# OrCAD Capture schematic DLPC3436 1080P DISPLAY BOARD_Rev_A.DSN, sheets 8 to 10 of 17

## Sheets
8 P12: DLPA3000 PMIC: size D
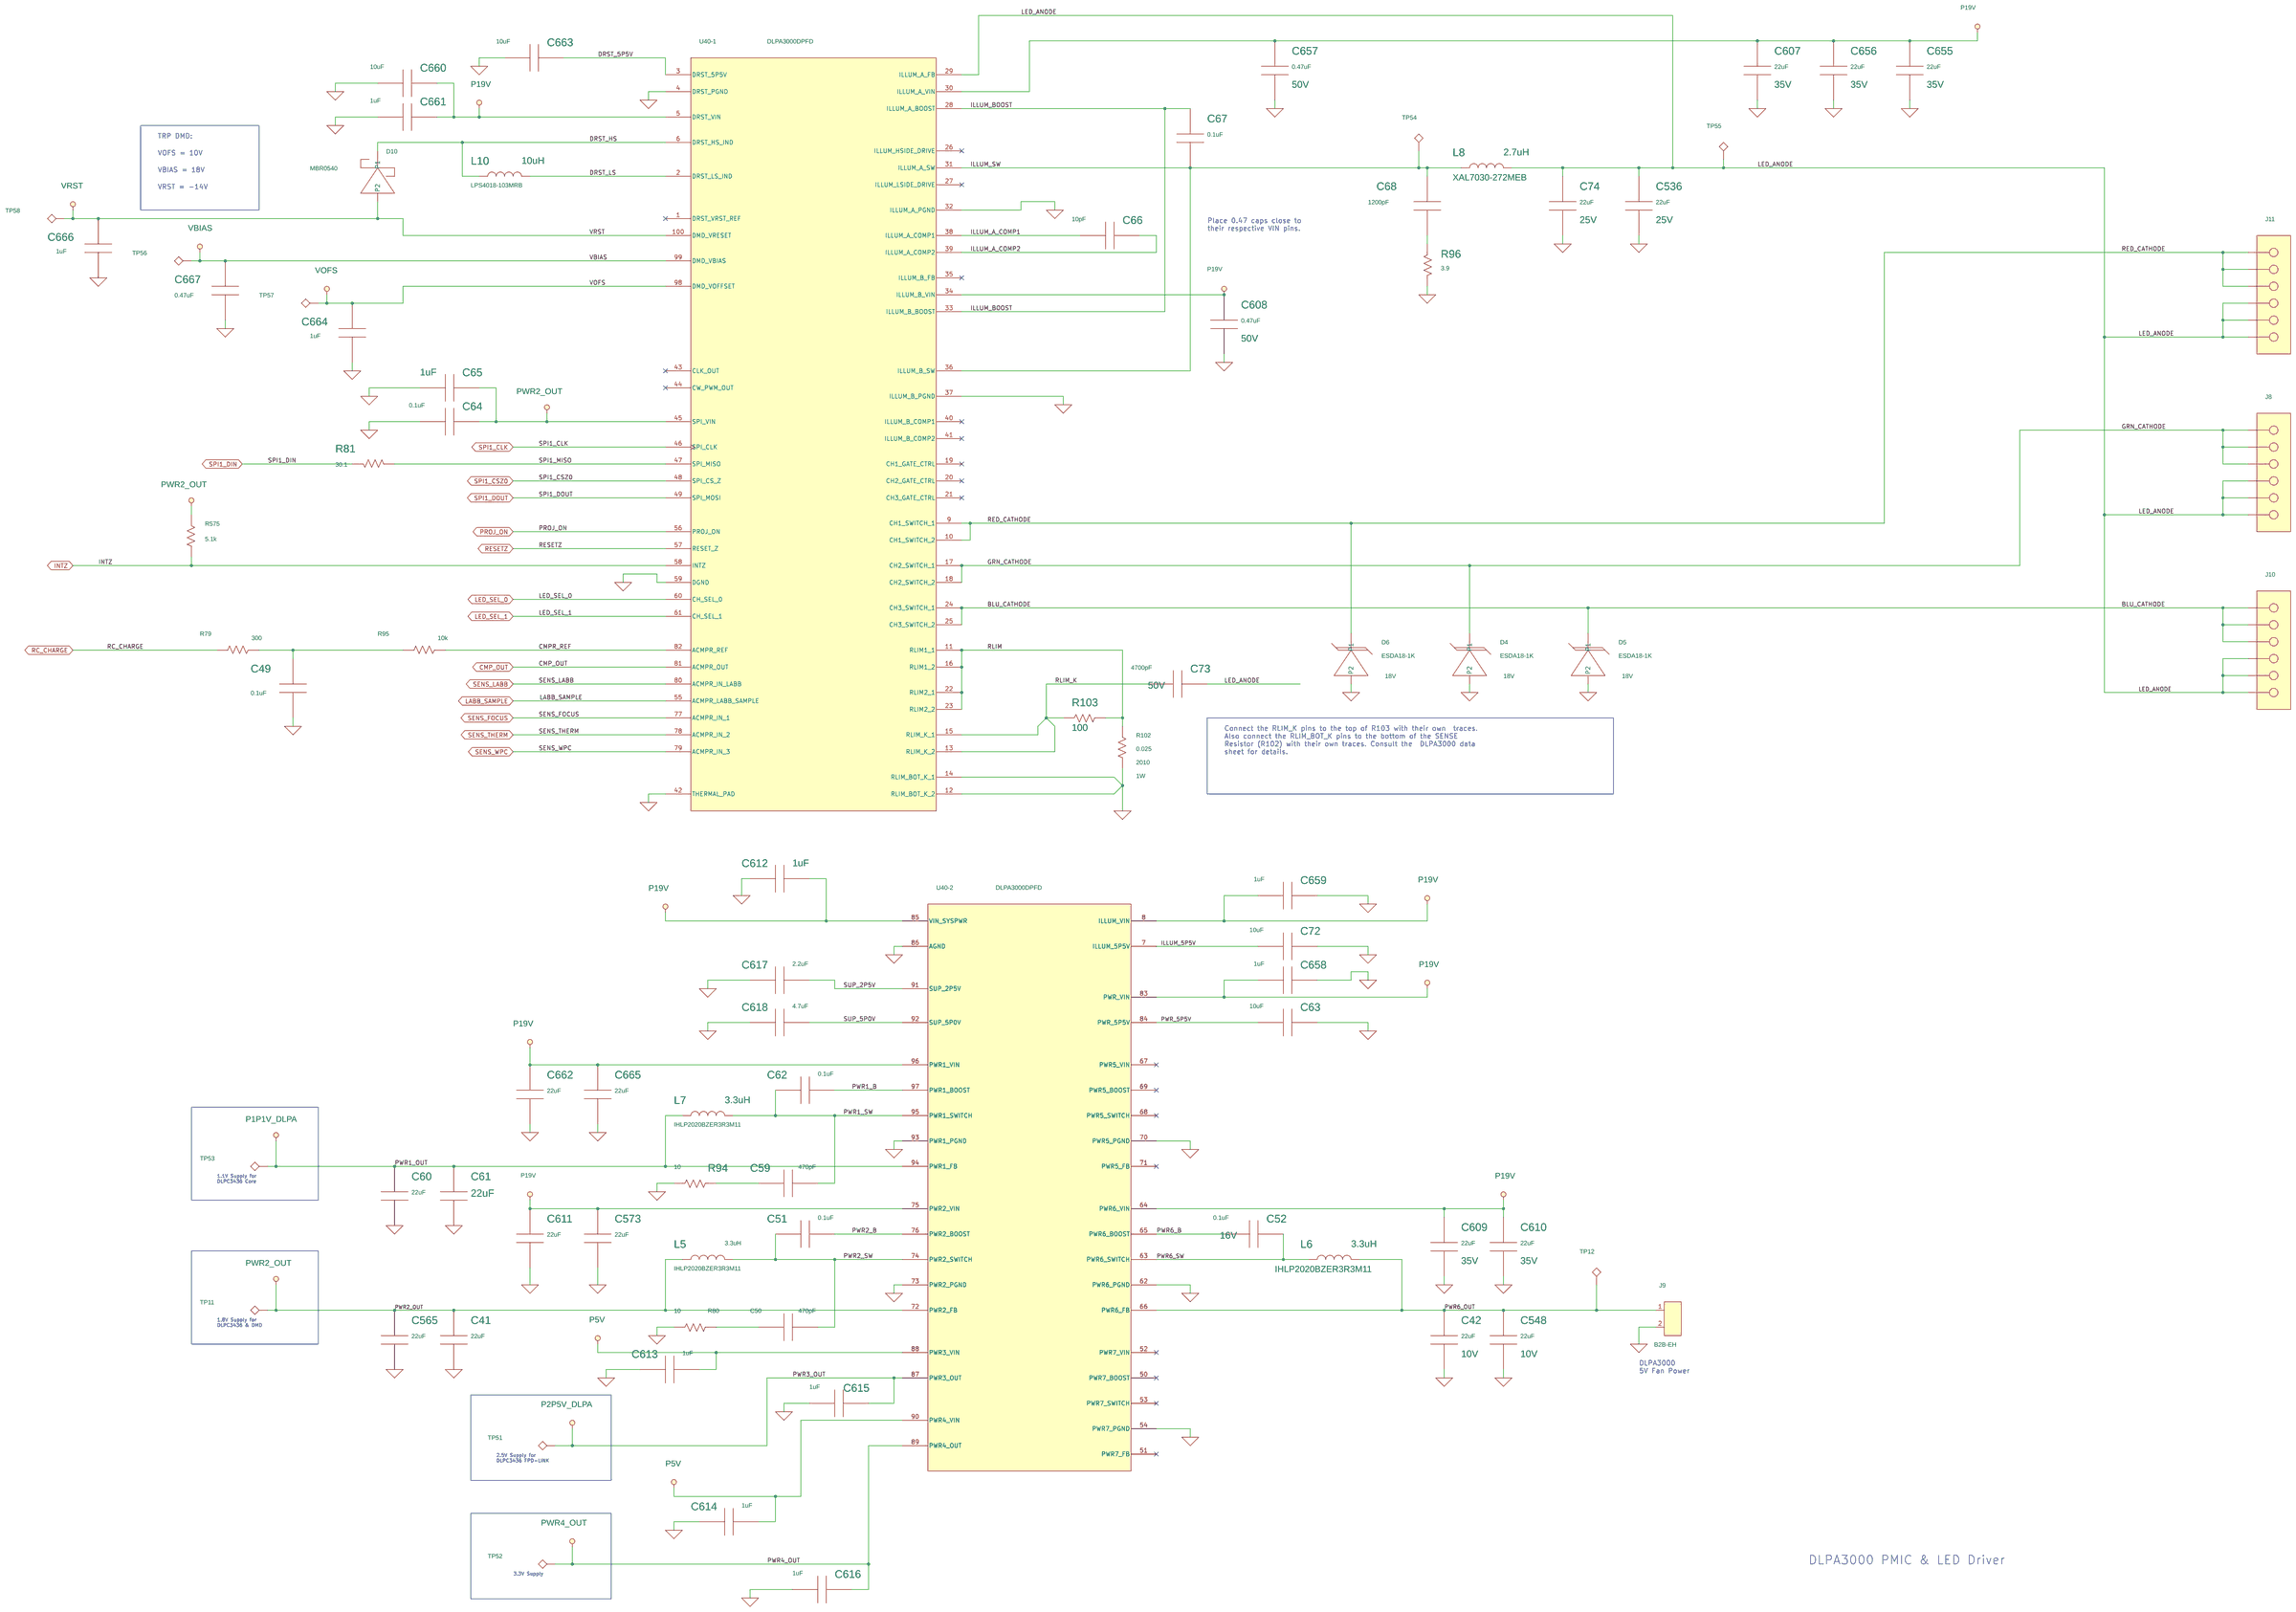
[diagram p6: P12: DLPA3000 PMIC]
9 P03: Parallel Video Input: size D
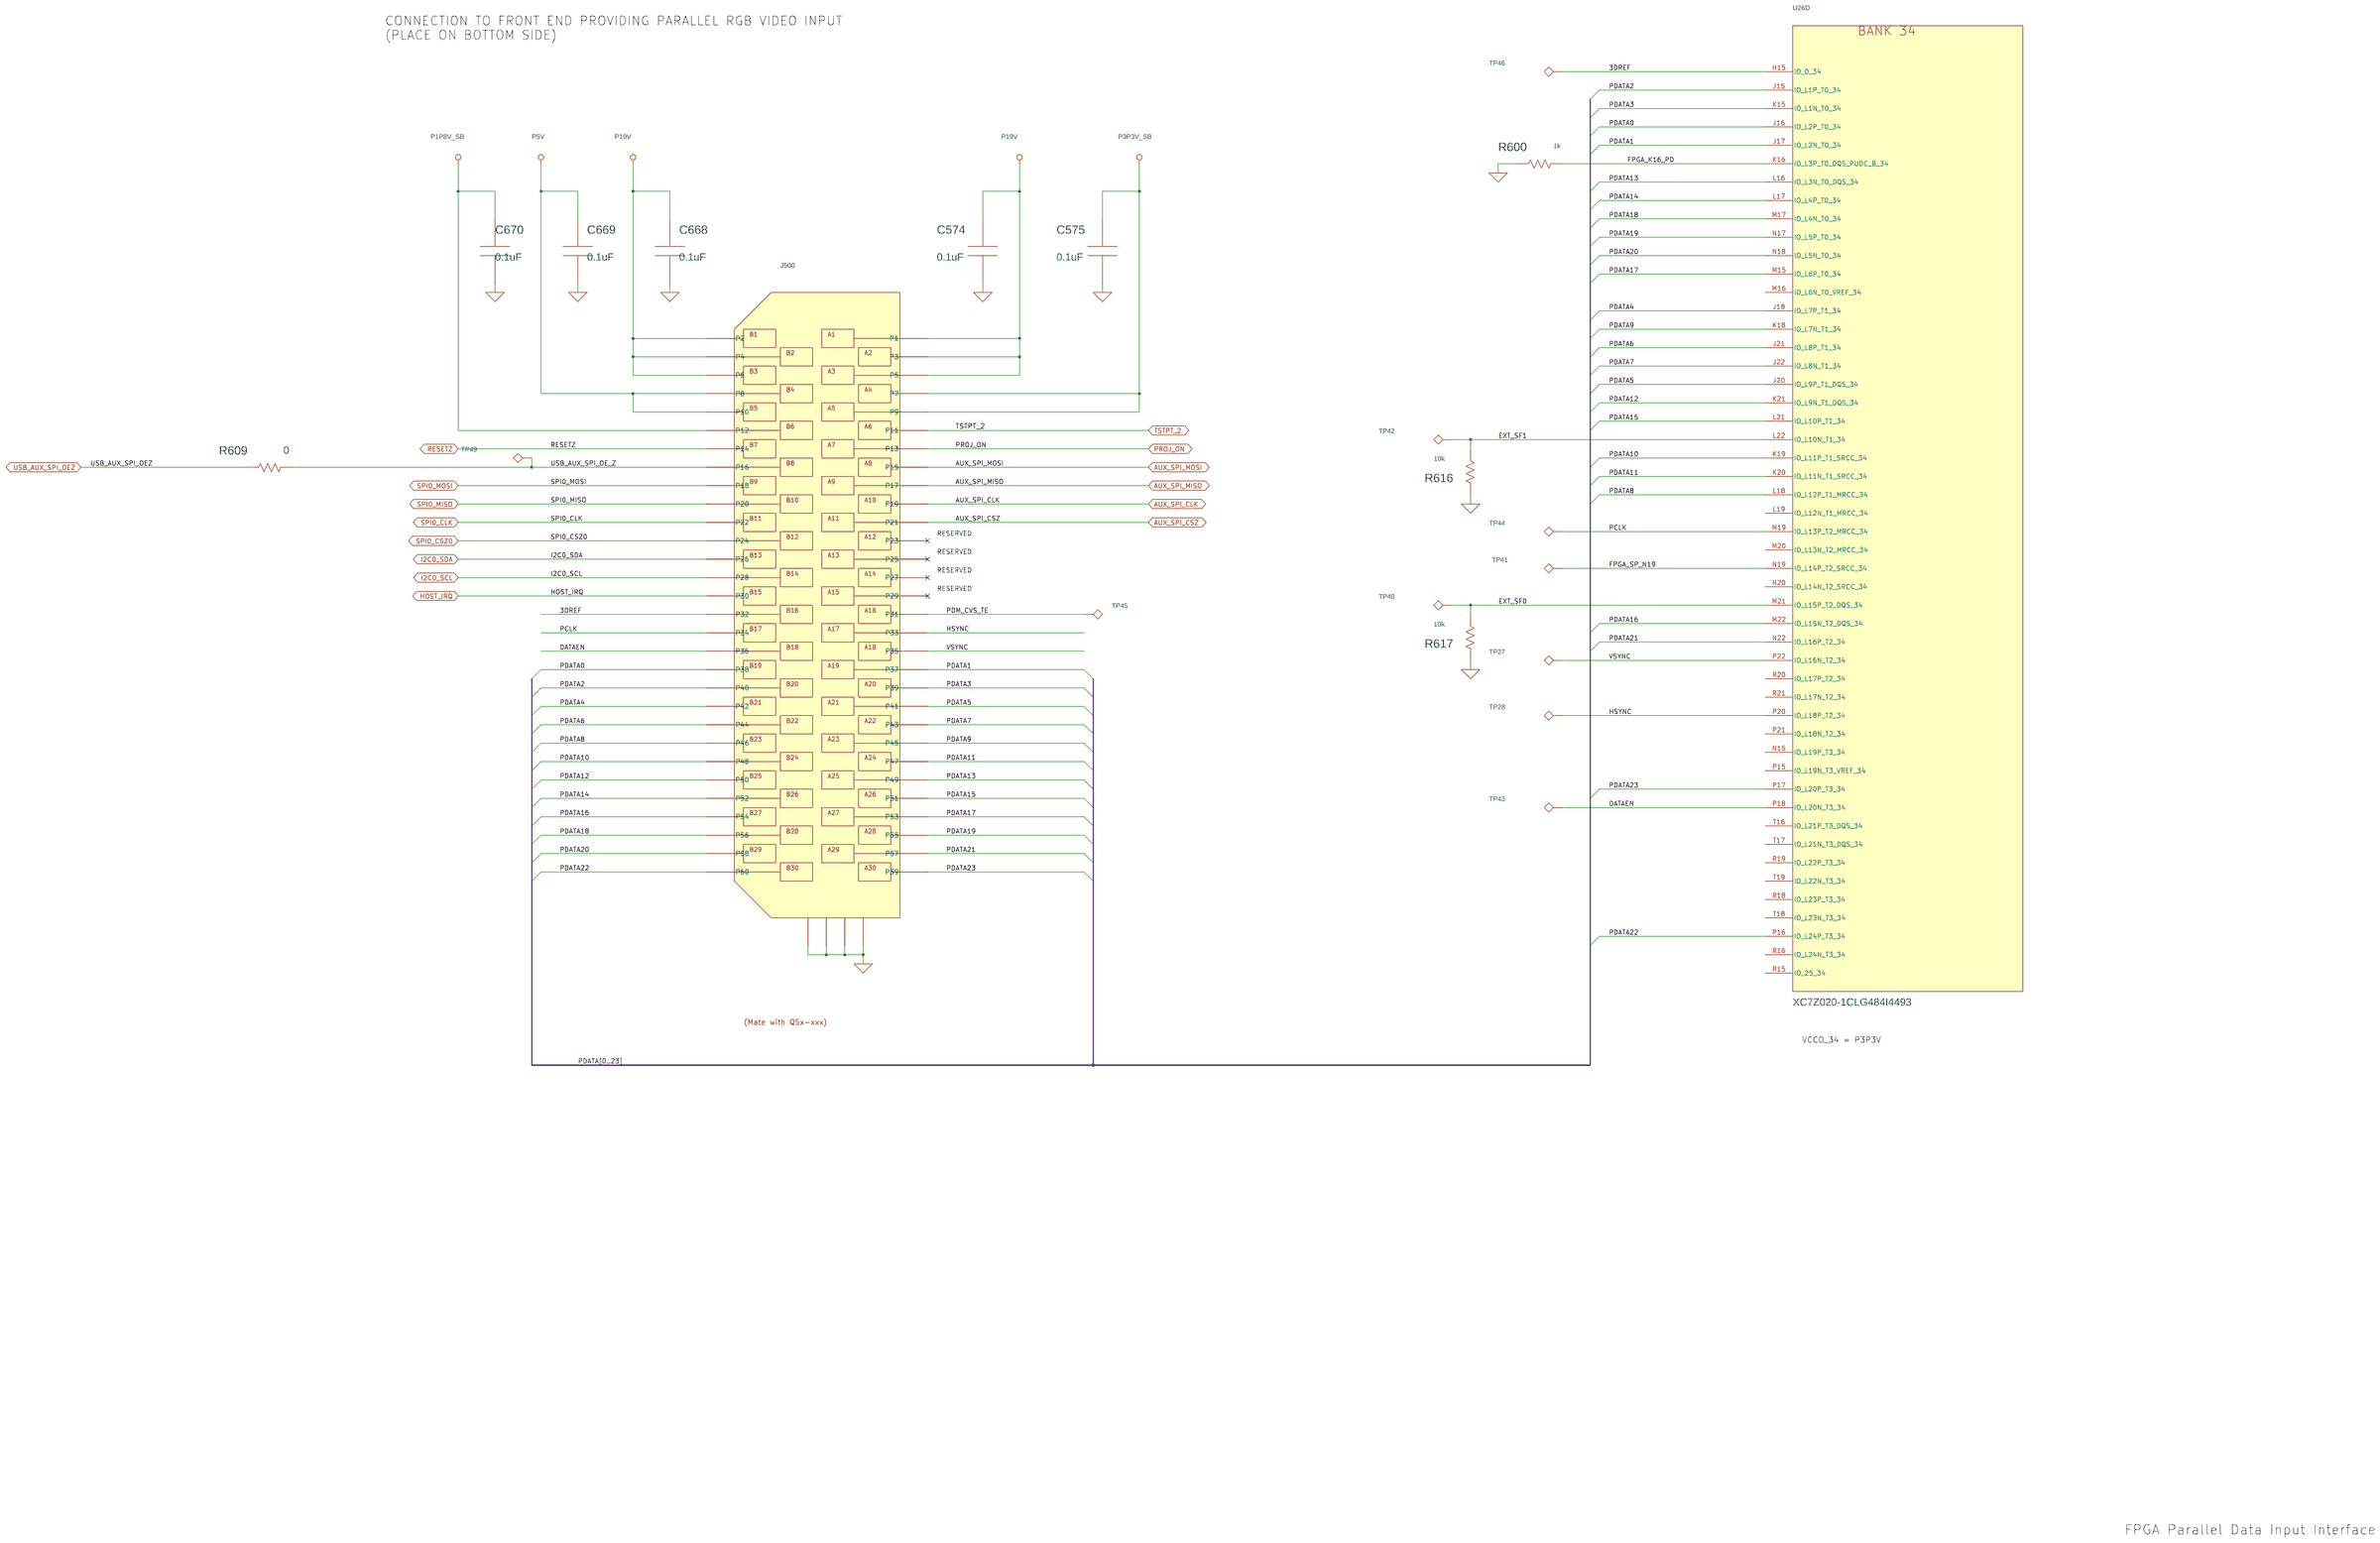
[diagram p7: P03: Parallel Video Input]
10 P14: Actuator Driver: size D
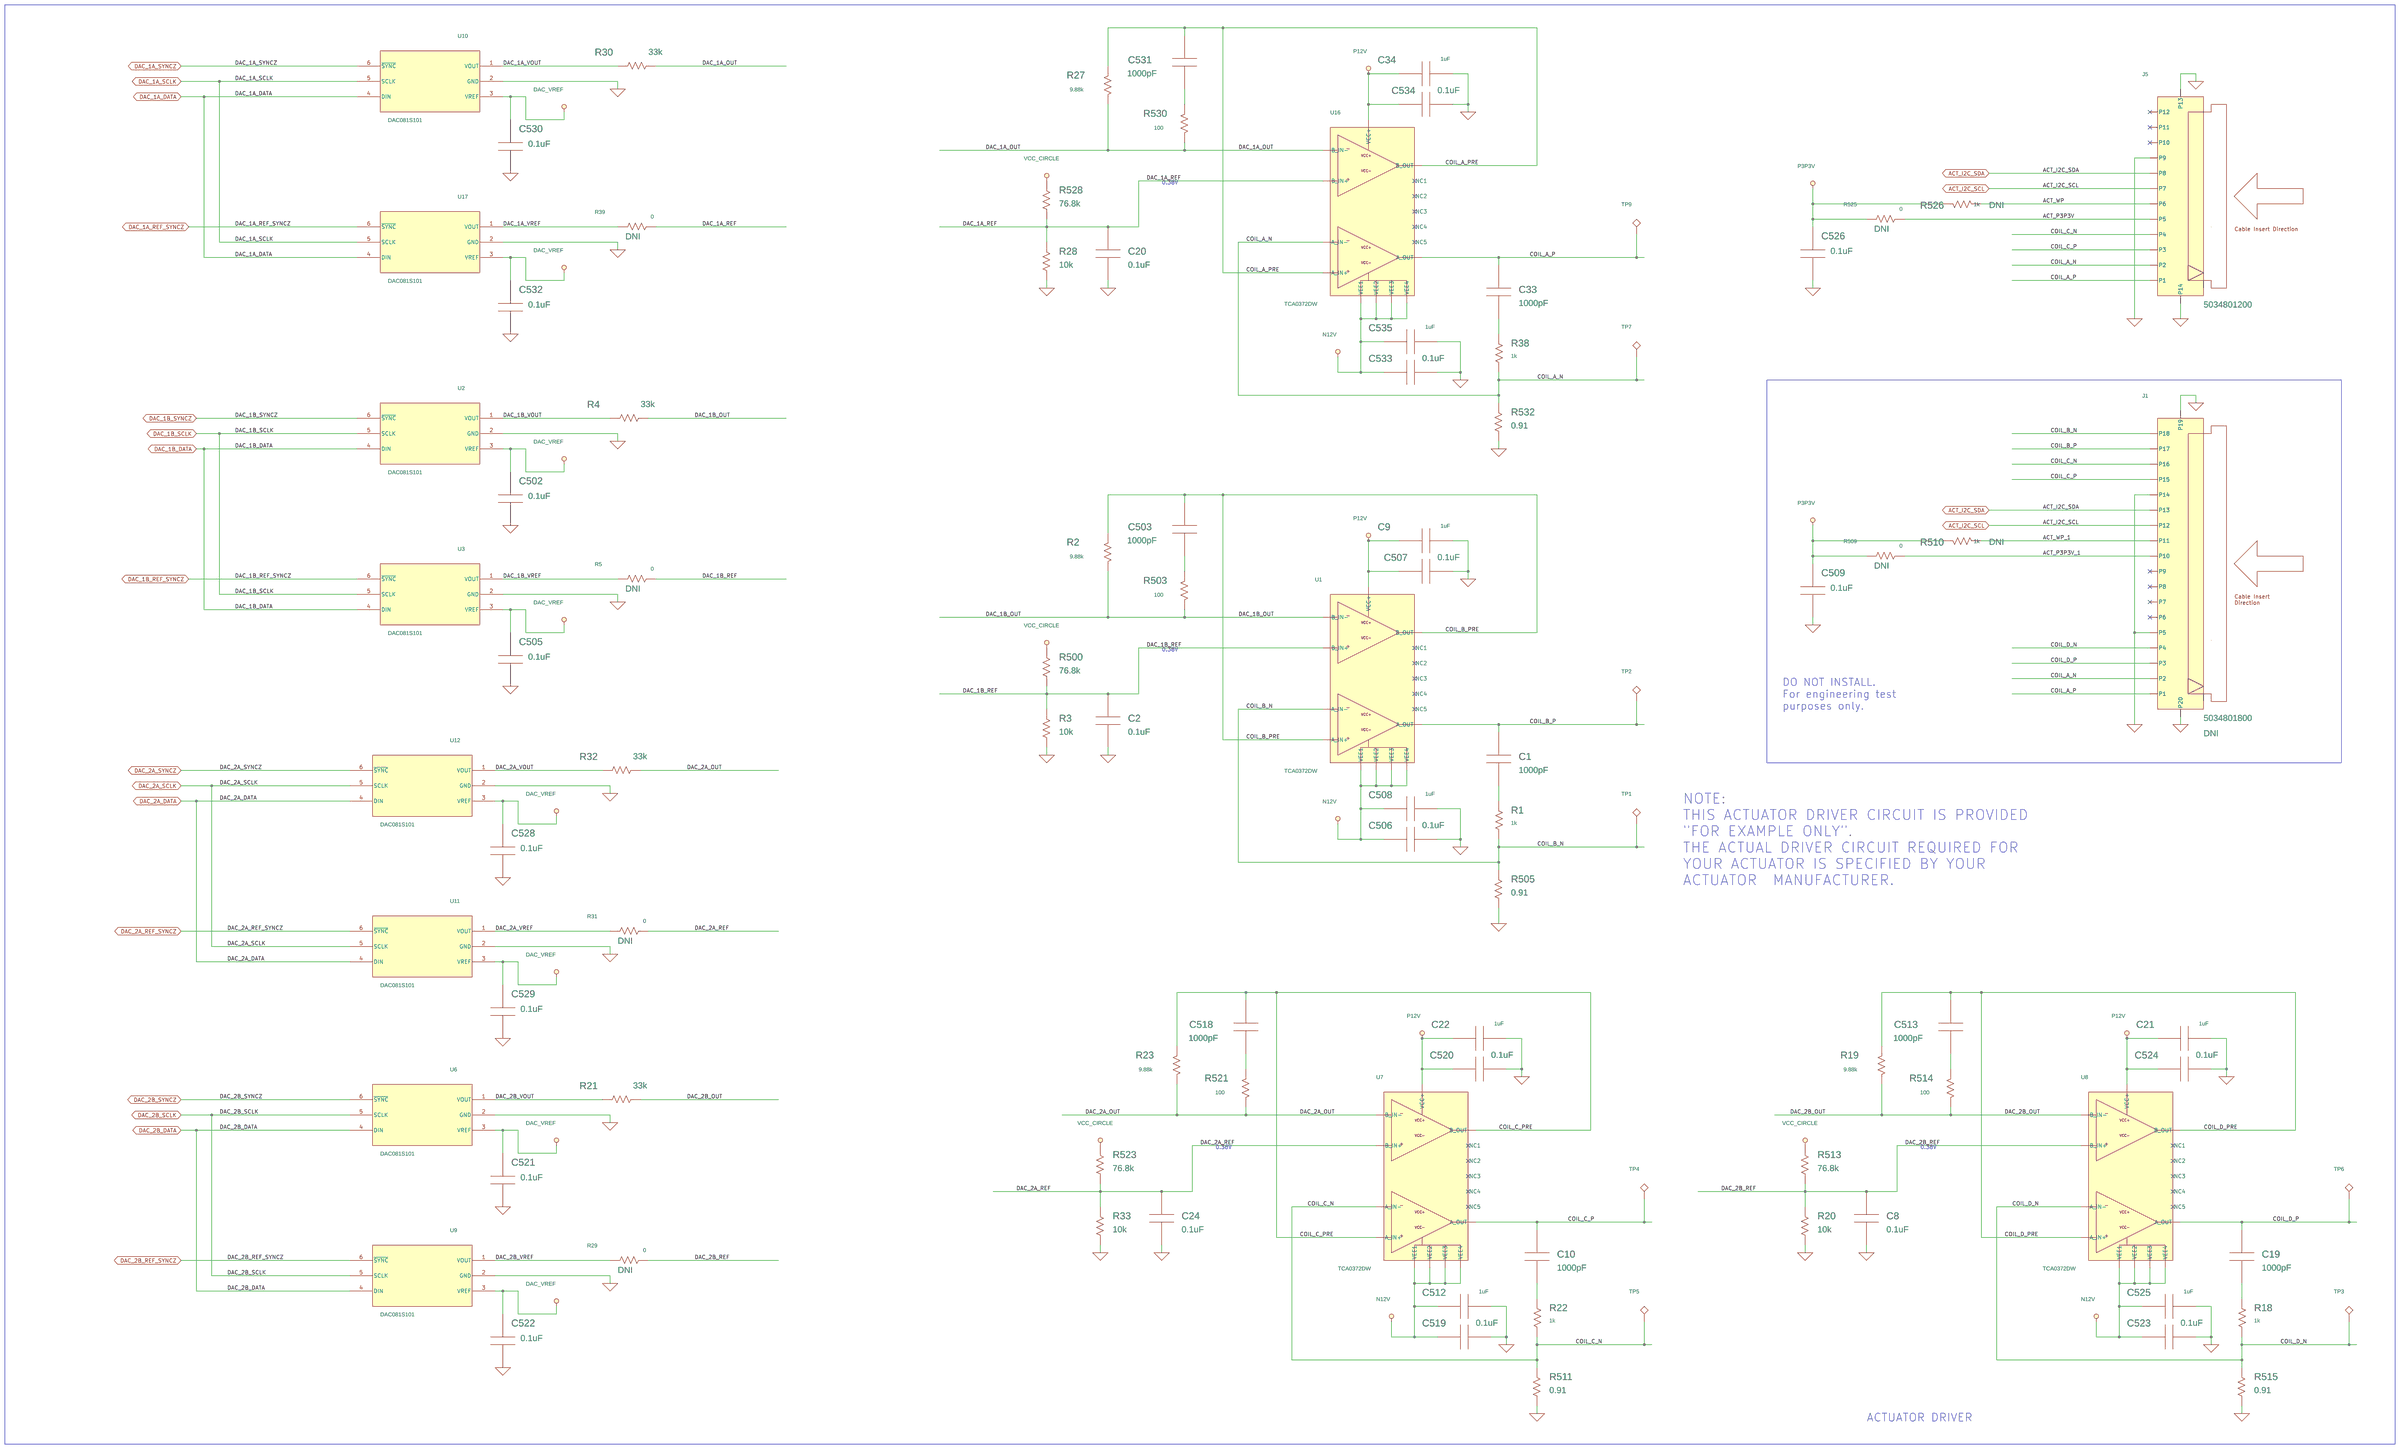
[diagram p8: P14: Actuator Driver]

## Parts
sheet P03: Parallel Video Input
C574  0.1uF  [0402_AVXA]
C575  0.1uF  [0402_AVXA]
C668  0.1uF  [0402_AVXA]
C669  0.1uF  [0402_AVXA]
C670  0.1uF  [0402_AVXA]
J500  QTH-030-03-L-D-A  [Samtec_QTH-030-xx-x-D-A]
R600  1k  [0402]
R609  0  [0402]
R616  10k  [0402]
R617  10k  [0402]
TP27  TP_WHT  [KEYSTONE_TP_MINIATURE]
TP28  TP40  [TP40]
TP40  TP40  [TP40]
TP41  TP,12mil Drill,32mil Pad  [HOLE_PLATED_12mil_DRILL_32mil_PAD]
TP42  TP40  [TP40]
TP43  TP40  [TP40]
TP44  TP40  [TP40]
TP45  TP,12mil Drill,32mil Pad  [HOLE_PLATED_12mil_DRILL_32mil_PAD]
TP46  TP40  [TP40]
TP49  TP,12mil Drill,32mil Pad  [HOLE_PLATED_12mil_DRILL_32mil_PAD]
U26  XC7Z020-1CLG484I4493  [Xilinx_CLG484]  (sections A,B,C,D,E,F,G,H,I,J)
sheet P12: DLPA3000 PMIC
C41  22uF  [0603]
C42  22uF  [0603]
C49  0.1uF  [0402_AVXA]
C50  470pF  [0603]
C51  0.1uF  [0402_AVXA]
C52  0.1uF  [0402_AVXA]
C59  470pF  [0603]
C60  22uF  [0603]
C61  22uF  [0603]
C62  0.1uF  [0402_AVXA]
C63  10uF  [0603]
C64  0.1uF  [0402_AVXA]
C65  1uF  [0402]
C66  10pF  [0402_AVXA]
C67  0.1uF  [0402_AVXA]
C68  1200pF  [1206]
C72  10uF  [0603]
C73  4700pF  [0402]
C74  22uF  [1210]
C536  22uF  [1210]
C548  22uF  [0603]
C565  22uF  [0603]
C573  22uF  [0805]
C607  22uF  [1210]
C608  0.47uF  [0402]
C609  22uF  [0805]
C610  22uF  [0805]
C611  22uF  [0805]
C612  1uF  [0402]
C613  1uF  [0402]
C614  1uF  [0402]
C615  1uF  [0402]
C616  1uF  [0402]
C617  2.2uF  [0402]
C618  4.7uF  [0402]
C655  22uF  [1210]
C656  22uF  [1210]
C657  0.47uF  [0402]
C658  1uF  [0402]
C659  1uF  [0402]
C660  10uF  [0805]
C661  1uF  [0402]
C662  22uF  [0805]
C663  10uF  [0603]
C664  1uF  [0603]
C665  22uF  [0805]
C666  1uF  [0603]
C667  0.47uF  [0603]
D4  ESDA18-K  [SOD523]
D5  ESDA18-K  [SOD523]
D6  ESDA18-K  [SOD523]
D10  MBR0540  [SOD123]
J8  087438-0643  [Molex_0874380643]
J9  B2B-EH  [JST_B2B_EH_A]
J10  087438-0643  [Molex_0874380643]
J11  087438-0643  [Molex_0874380643]
L5  3.3uH  [IHLP2020BZER]
L6  3.3uH  [IHLP2020BZER]
L7  3.3uH  [IHLP2020BZER]
L8  2.7uH  [Coilcraft_XAL70300]
L10  10uH  [Coilcraft_LPS4018_MR]
R79  300  [0402]
R80  10  [0603]
R81  30.1  [0402]
R94  10  [0603]
R95  10k  [0402]
R96  3.9  [1210]
R102  0.025  [2010]
R103  100  [0402]
R575  5.1k  [0402]
TP11  TP,40mil Drill,60mil Pad  [HOLE_PLATED_40mil_DRILL_60mil_PAD]
TP12  TP,40mil Drill,60mil Pad  [HOLE_PLATED_40mil_DRILL_60mil_PAD]
TP51  TP,40mil Drill,60mil Pad  [HOLE_PLATED_40mil_DRILL_60mil_PAD]
TP52  TP,40mil Drill,60mil Pad  [HOLE_PLATED_40mil_DRILL_60mil_PAD]
TP53  TP,40mil Drill,60mil Pad  [HOLE_PLATED_40mil_DRILL_60mil_PAD]
TP54  TP,40mil Drill,60mil Pad  [HOLE_PLATED_40mil_DRILL_60mil_PAD]
TP55  TP,40mil Drill,60mil Pad  [HOLE_PLATED_40mil_DRILL_60mil_PAD]
TP56  TP,40mil Drill,60mil Pad  [HOLE_PLATED_40mil_DRILL_60mil_PAD]
TP57  TP,40mil Drill,60mil Pad  [HOLE_PLATED_40mil_DRILL_60mil_PAD]
TP58  TP,40mil Drill,60mil Pad  [HOLE_PLATED_40mil_DRILL_60mil_PAD]
U40  DLPA3000  [PAD3000_PQFP_100]  (sections -1,-2)
sheet P14: Actuator Driver
C1  1000pF  [0603]
C2  0.1uF  [0805]
C8  0.1uF  [0805]
C9  1uF  [0402]
C10  1000pF  [0603]
C19  1000pF  [0603]
C20  0.1uF  [0805]
C21  1uF  [0402]
C22  1uF  [0402]
C24  0.1uF  [0805]
C33  1000pF  [0603]
C34  1uF  [0402]
C502  0.1uF  [0402]
C503  1000pF  [0603]
C505  0.1uF  [0402]
C506  0.1uF  [0402]
C507  0.1uF  [0402]
C508  1uF  [0402]
C509  0.1uF  [0402]
C512  1uF  [0402]
C513  1000pF  [0603]
C518  1000pF  [0603]
C519  0.1uF  [0402]
C520  0.1uF  [0402]
C521  0.1uF  [0402]
C522  0.1uF  [0402]
C523  0.1uF  [0402]
C524  0.1uF  [0402]
C525  1uF  [0402]
C526  0.1uF  [0402]
C528  0.1uF  [0402]
C529  0.1uF  [0402]
C530  0.1uF  [0402]
C531  1000pF  [0603]
C532  0.1uF  [0402]
C533  0.1uF  [0402]
C534  0.1uF  [0402]
C535  1uF  [0402]
J1  5034801800  [Molex_5034801800_2GPADS]
J5  5034801200  [Molex_5034801200_2GPADS]
R1  1k  [0603]
R2  9.88k  [0805]
R3  10k  [0603]
R4  33k  [0402]
R5  0  [0402]
R18  1k  [0603]
R19  9.88k  [0805]
R20  10k  [0603]
R21  33k  [0402]
R22  1k  [0603]
R23  9.88k  [0805]
R27  9.88k  [0805]
R28  10k  [0603]
R29  0  [0402]
R30  33k  [0402]
R31  0  [0402]
R32  33k  [0402]
R33  10k  [0603]
R38  1k  [0603]
R39  0  [0402]
R500  76.8k  [0603]
R503  100  [0603]
R505  0.91  [0805]
R509  0  [0402]
R510  1k  [0402]
R511  0.91  [0805]
R513  76.8k  [0603]
R514  100  [0603]
R515  0.91  [0805]
R521  100  [0603]
R523  76.8k  [0603]
R525  0  [0402]
R526  1k  [0402]
R528  76.8k  [0603]
R530  100  [0603]
R532  0.91  [0805]
TP1  TP,40mil Drill,60mil Pad  [HOLE_PLATED_40mil_DRILL_60mil_PAD]
TP2  TP,40mil Drill,60mil Pad  [HOLE_PLATED_40mil_DRILL_60mil_PAD]
TP3  TP,40mil Drill,60mil Pad  [HOLE_PLATED_40mil_DRILL_60mil_PAD]
TP4  TP,40mil Drill,60mil Pad  [HOLE_PLATED_40mil_DRILL_60mil_PAD]
TP5  TP,40mil Drill,60mil Pad  [HOLE_PLATED_40mil_DRILL_60mil_PAD]
TP6  TP,40mil Drill,60mil Pad  [HOLE_PLATED_40mil_DRILL_60mil_PAD]
TP7  TP,40mil Drill,60mil Pad  [HOLE_PLATED_40mil_DRILL_60mil_PAD]
TP9  TP,40mil Drill,60mil Pad  [HOLE_PLATED_40mil_DRILL_60mil_PAD]
U1  TCA0372DW  [ONSEMI_SOIC16W_DW_CASE751G]
U2  DAC081S101  [SOT-23-6_DDC_R-PDSO-G6]
U3  DAC081S101  [SOT-23-6_DDC_R-PDSO-G6]
U6  DAC081S101  [SOT-23-6_DDC_R-PDSO-G6]
U7  TCA0372DW  [ONSEMI_SOIC16W_DW_CASE751G]
U8  TCA0372DW  [ONSEMI_SOIC16W_DW_CASE751G]
U9  DAC081S101  [SOT-23-6_DDC_R-PDSO-G6]
U10  DAC081S101  [SOT-23-6_DDC_R-PDSO-G6]
U11  DAC081S101  [SOT-23-6_DDC_R-PDSO-G6]
U12  DAC081S101  [SOT-23-6_DDC_R-PDSO-G6]
U16  TCA0372DW  [ONSEMI_SOIC16W_DW_CASE751G]
U17  DAC081S101  [SOT-23-6_DDC_R-PDSO-G6]

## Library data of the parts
C574 C575 C668-C670 = PAS,CAP,NP,large: DigiKey: 445-4952-1-ND; DigiReel: 445-4952-6-ND; Family: passive; Index PN: 681; Lead Style: SMT; MFG: TDK; Material: x7r; P/D_NUM: C1005X7R1C104K050BC; Part Number: C1005X7R1C104K050BC; Part Specific: CAP CER .1UF 16V X7R 0402; TOLERANCE: 10%; Type: capacitor; VENDOR: TDK; VPC: 16V
J500 = EM,CONN,60P,QTx: DigiKey: SAM8187-ND; Family: electro/mechanical; Index PN: 1197; Lead Style: SMT; MFG: Samtec; Part Specific: CONN HEADER HS .5MM 60POS DL AU (stacking ht 11mm); Pin Cnt: 60; Pin Spacing: 0.5mm; Row Cnt: 2; Type: connector; Vendor: Samtec
R600 = PAS,R,large: DigiKey: P1.00KLCT-ND; DigiReel: P1.00KLDKR-ND; Family: passive; Index PN: 684; Install: Y; Lead Style: SMT; MFG: Panasonic; Material: chip; P/D_NUM: ERJ-2RKF1001X; Part Number: ERJ-2RKF1001X; Part Specific: RES 1.00K OHM 1/10W 1% 0402 SMD; Power: 1/16W; TOLERANCE: 1%; Type: resistor; VENDOR: Panasonic; VPC: 1/16W
R609 = PAS,R,large: DigiKey: P0.0JCT-ND; DigiReel: P0.0JDKR-ND; Family: passive; Index PN: 687; Install: Y; Lead Style: SMT; MFG: Panasonic; Material: chip; P/D_NUM: ERJ-2GE0R00X; Part Number: ERJ-2GE0R00X; Part Specific: RES 0.0 OHM 1/16W 0402 SMD; Power: 1/16W; Type: resistor; VPC: 1/16W; Vendor: Panasonic
R616 R617 = PAS,R,large: DigiKey: P10.0KLCT-ND; DigiReel: P10.0KLDKR-ND; Family: passive; Index PN: 680; Install: Y; Lead Style: SMT; MFG: Panasonic; Material: chip; P/D_NUM: ERJ-2RKF1002X; Part Number: ERJ-2RKF1002X; Part Specific: RES SMD 10K OHM 1% 1/10W 0402; Power: 1/16W; TOLERANCE: 1%; Type: resistor; VENDOR: Panasonic; VPC: 1/16W
TP27 = EM,TERM,TESTPOINT: DigiKey: 36-5002-ND; DigiReel: ---; Family: electro/mechanical; Install: DNI; Lead Style: TH; MFG: Keystone; P/D_NUM: 5002; Part Number: 5002; Part Specific: TEST POINT PC MINI .040inD WHITE; Type: terminal; Vendor: Keystone
TP28 TP40 TP42-TP44 TP46 = EM,TERM,TESTPOINT: DigiKey: ---; DigiReel: ---; Family: board feature; Index PN: 995; Install: DNI; MFG: -- NOT A PART --; Type: hole,plated; Vendor: -- NOT A PART --
TP41 TP45 TP49 = EM,TERM,TESTPOINT: Family: board feature; Index PN: 122; Install: DNI; MFG: -- NOT A PART --; Type: hole,plated; Vendor: -- NOT A PART --
U26 = TIDLP,XPR_FPGA,Zynq-7020new_0: DigiKey: ---; DigiReel: ---; Family: processor; Index PN: 1304; Lead Style: SMT; MFG: Xilinx; Type: dlp; Vendor: Xilinx
C41 C60 C61 C565 = PAS,CAP,NP,large: DigiKey: 445-8028-1-ND; DigiReel: 445-8028-6-ND; Family: passive; Lead Style: SMT; MFG: TDK; Material: X5R; P/D_NUM: C1608X5R0J226M080AC; Part Number: C1608X5R0J226M080AC; Part Specific: CAP CER 22UF 6.3V 20% X5R 0603; TOLERANCE: 20%; Type: capacitor; VENDOR: TDK; VPC: 6.3V; Voltage: 6.3V
C42 C548 = PAS,CAP,NP,large: DigiKey: 445-9077-1-ND; DigiReel: 445-9077-6-ND; Family: passive; Lead Style: SMT; MFG: TDK; Material: X5R; P/D_NUM: C1608X5R1A226M080AC; Part Number: C1608X5R1A226M080AC; Part Specific: CAP CER 22UF 10V 20% X5R 0603; TOLERANCE: 20%; Type: capacitor; VENDOR: TDK; VPC: 10V; Voltage: 10V
C49 = PAS,CAP,NP,large: DigiKey: 445-4952-1-ND; DigiReel: 445-4952-6-ND; Family: passive; Index PN: 681; Lead Style: SMT; MFG: TDK; Material: x7r; P/D_NUM: C1005X7R1C104K050BC; Part Number: C1005X7R1C104K050BC; Part Specific: CAP CER .1UF 16V X7R 0402; TOLERANCE: 10%; Type: capacitor; VENDOR: TDK; VPC: 16V; Voltage: 25V
C50 C59 = PAS,CAP,NP,large: DigiKey: 445-1289-1-ND; DigiReel: 445-1289-6-ND; Family: passive; Install: Y; Lead Style: SMT; MFG: TDK; Material: npo; P/D_NUM: C1608C0G1H471J080AA; Part Number: C1608C0G1H471J080AA; Part Specific: CAP CER 470PF 50V 5% NP0 0603; TOLERANCE: 5%; Type: capacitor; VENDOR: TDK; VPC: 50V; Voltage: 50V
C51 C52 C62 C64 C67 = PAS,CAP,NP,large: DigiKey: 445-4952-1-ND; DigiReel: 445-4952-6-ND; Family: passive; Index PN: 681; Lead Style: SMT; MFG: TDK; Material: x7r; P/D_NUM: C1005X7R1C104K050BC; Part Number: C1005X7R1C104K050BC; Part Specific: CAP CER .1UF 16V X7R 0402; TOLERANCE: 10%; Type: capacitor; VENDOR: TDK; VPC: 16V; Voltage: 16V
C63 C72 C663 = PAS,CAP,NP,large: DigiKey: 445-6853-1-ND; DigiReel: 445-6853-6-ND; Family: passive; Index PN: 1207; Lead Style: SMT; MFG: TDK; P/D_NUM: C1608X5R1A106M080AC; Part Number: C1608X5R1A106M080AC; Part Specific: CAP CER 10UF 10V 20% X5R 0603; TOLERANCE: 20%; Type: capacitor; VENDOR: TDK; VPC: 10V; Voltage: 10V
C65 C615 C616 = PAS,CAP,NP,large: DigiKey: 1276-1448-1-ND; DigiReel: 1276-1448-6-ND; Family: passive; Lead Style: SMT; MFG: Samsung; Material: x5r; P/D_NUM: CL05A105MP5NNNC; Part Number: CL05A105MP5NNNC; Part Specific: CAP CER 1.0UF 10V X5R 0402; TOLERANCE: 20%; Type: capacitor; VENDOR: Samsung; VPC: 10V
C66 = PAS,CAP,NP,large: DigiKey: 445-1235-1-ND; DigiReel: 445-1235-6-ND; Family: passive; Install: Y; Lead Style: SMT; MFG: TDK; Material: npo; P/D_NUM: C1005C0G1H100D050BA; Part Number: C1005C0G1H100D050BA; Part Specific: CAP CER 10PF 50V NP0 0402; TOLERANCE: +/-0.5pF; Type: capacitor; VENDOR: TDK; VPC: 50V; Voltage: 50V
C68 = PAS,CAP,NP,large: DigiKey: 478-1493-1-ND; DigiReel: 478-1493-6-ND; Family: passive; Install: Y; Lead Style: SMT; MFG: AVX; Material: npo; P/D_NUM: 12065A122JAT2A; Part Number: 12065A122JAT2A; Part Specific: CAP CER 1200PF 50V 5% NP0 1206; TOLERANCE: 5%; Type: capacitor; VENDOR: AVX; VPC: 50V; Voltage: 50V
C73 = PAS,CAP,NP,large: DigiKey: 490-14739-1-ND; DigiReel: 490-14739-6-ND; Family: passive; Install: Y; Lead Style: SMT; MFG: Murata; Material: x7r; P/D_NUM: GCM155R71H472KA37J; Part Number: GCM155R71H472KA37J; Part Specific: CAP CER 4700PF 50V 10% X7R 0402; TOLERANCE: 10%; Type: capacitor; VENDOR: Murata; VPC: 50V; Voltage: 50V
C74 C536 = PAS,CAP,NP,large: DigiKey: 490-6540-1-ND; DigiReel: 490-6540-6-ND; Family: passive; Index PN: 1406; Lead Style: SMT; MFG: Murata; Material: x5r; P/D_NUM: GRM32ER61E226KE15K; Part Number: GRM32ER61E226KE15K; Part Specific: CAP CER 22UF 25V 10% X5R 1210; TOLERANCE: 10%; Type: capacitor; VENDOR: Murata; VPC: 25V; Voltage: 25V
C573 C611 C662 C665 = PAS,CAP,NP,large: DigiKey: 445-14428-1-ND; DigiReel: 445-14428-6-ND; Family: passive; Lead Style: SMT; MFG: TDK; Material: x5r; P/D_NUM: C2012X5R1V226M125AC; Part Number: C2012X5R1V226M125AC; Part Specific: CAP CER 22UF 35V 20% X5R 0805; TOLERANCE: 20%; Type: capacitor; VENDOR: TDK; VPC: 35V; Voltage: 35V
C607 C655 C656 = PAS,CAP,NP,large: DigiKey: 587-6141-1-ND; DigiReel: 587-6141-6-ND; Family: passive; Lead Style: SMT; MFG: Taiyo Yuden; Material: x5r; P/D_NUM: GMK325BJ226MM-T; Part Number: GMK325BJ226MM-T; Part Specific: CAP CER 22UF 35V 20% X5R 1210; TOLERANCE: 20%; Type: capacitor; VENDOR: Taiyo Yuden; VPC: 35V; Voltage: 35V
C608 C657 = PAS,CAP,NP,large: DigiKey: 587-3497-1-ND; DigiReel: 587-3497-6-ND; Family: passive; Lead Style: SMT; MFG: Taiyo Yuden; P/D_NUM: UMK105ABJ474KV-F; Part Number: UMK105ABJ474KV-F; Part Specific: CAP CER 0.47UF 50V 10% X5R 0402; TOLERANCE: 10%; Type: capacitor; VENDOR: Taiyo Yuden; VPC: 50V; Voltage: 50V
C609 C610 = PAS,CAP,NP,large: DigiKey: 445-14428-1-ND; DigiReel: 445-14428-6-ND; Family: passive; Lead Style: SMT; MFG: TDK; Material: X5R; P/D_NUM: C2012X5R1V226M125AC; Part Number: C2012X5R1V226M125AC; Part Specific: CAP CER 22UF 35V 20% X5R 0805; TOLERANCE: 20%; Type: capacitor; VENDOR: TDK; VPC: 35V; Voltage: 35V
C9 C21 C22 C34 C508 C512 C525 C535 C612-C614 C658 C659 C661 = PAS,CAP,NP,large: DigiKey: 445-9081-1-ND; DigiReel: 445-9081-6-ND; Family: passive; Index PN: 1278; Lead Style: SMT; MFG: TDK; P/D_NUM: C1005X5R1E105M050BC; Part Number: C1005X5R1E105M050BC; Part Specific: CAP CER 1UF 25V 20% X5R 0402; TOLERANCE: 20%; Type: capacitor; VENDOR: TDK; VPC: 25V; Voltage: 25V
C617 = PAS,CAP,NP,large: DigiKey: 445-4999-1-ND; DigiReel: 445-4999-6-ND; Family: passive; Index PN: 915; Lead Style: SMT; MFG: TDK; Material: x5r; P/D_NUM: C1005X5R0J225M; Part Number: C1005X5R0J225M; Part Specific: CAP CER 2.2UF 6.3V 20% X5R 0402; TOLERANCE: 20%; Type: capacitor; VENDOR: TDK; VPC: 6.3V; Voltage: 6.3V
C618 = PAS,CAP,NP,large: DigiKey: 445-7395-1-ND; DigiReel: 445-7395-6-ND; Family: passive; Index PN: 1073; Lead Style: SMT; MFG: TDK; Material: x5r; P/D_NUM: C1005X5R0J475M; Part Number: C1005X5R0J475M; Part Specific: CAP CER 4.7UF 6.3V 20% X5R 0402; Type: capacitor; VENDOR: TDK; VPC: 6.3V; Voltage: 10V
C660 = PAS,CAP,NP,large: DigiKey: 445-14419-1-ND; DigiReel: 445-14419-6-ND; Family: passive; Index PN: 1288; Lead Style: SMT; MFG: TDK; Material: x5r; P/D_NUM: C2012X5R1V106M085AC; Part Number: C2012X5R1V106M085AC; Part Specific: CAP CER 10UF 35V 20% X5R 0805; TOLERANCE: 20%; Type: capacitor; VENDOR: TDK; VPC: 35V; Voltage: 25V
C664 C666 = PAS,CAP,NP,large: DigiKey: 1276-1860-1-ND; DigiReel: 1276-1860-6-ND; Family: passive; Lead Style: SMT; MFG: Samsung; Material: X5R; P/D_NUM: CL10A105KB8NNNC; Part Number: CL10A105KB8NNNC; Part Specific: CAP CER 1UF 50V 10% X5R 0603; TOLERANCE: 10%; Type: capacitor; VENDOR: Samsung; VPC: 50V; Voltage: 50V
C667 = PAS,CAP,NP,large: DigiKey: 445-7464-1-ND; DigiReel: 445-7464-6-ND; Family: passive; Lead Style: SMT; MFG: TDK; Material: X5R; P/D_NUM: C1608X5R1H474K080AB; Part Number: C1608X5R1H474K080AB; Part Specific: CAP CER 0.47UF 50V 10% X5R 0603; TOLERANCE: 10%; Type: capacitor; VENDOR: TDK; VPC: 50V; Voltage: 50V
D4-D6 = PAS,DIODE,TVS,large: DigiKey: 497-10767-1-ND; DigiReel: 497-10767-6-ND; Family: passive; Index PN: 1275; Lead Style: SMT; MFG: STMicroelectronics; P/D_NUM: ESDA18-1K; Part Number: ESDA18-1K; Part Specific: TVS DIODE 15VWM 34VC SOD523; Type: diode,tvs; VENDOR: STMicroelectronics; Voltage: 18V
D10 = PAS,DIODE,SCHOTTKY,large: DigiKey: MBR0540CT-ND; DigiReel: MBR0540DKR-ND; Family: passive; Lead Style: SMT; MFG: Fairchild Semiconductor; Part Specific: SCHOTTKY RECT 40V 0.5A SOD123; Type: diode,schottky; VENDOR: Fairchild Semiconductor; VPC: 0.5A; Voltage: 40V
J8 J10 J11 = EM,HDR,6P,1R,2X: DigiKey: WM7650CT-ND; DigiReel: WM7650DKR-ND; Family: electro/mechanical; Lead Style: SMT; MFG: Molex; P/D_NUM: 0874380643; Part Number: 0874380643; Part Specific: CONN HEADER 6POS 1.5MM R/A SMD; Pin Cnt: 6; Pin Spacing: 1.5mm; Row Cnt: 1; Type: header; Vendor: Molex
J9 = EM,HDR,2P,1R: DigiKey: 455-1611-ND; DigiReel: ---; Family: electro/mechanical; Lead Style: SMT; MFG: JST; P/D_NUM: B2B-EH-A(LF)(SN); Package: HDR_EH_A_2; Part Number: B2B-EH-A(LF)(SN); Part Specific: CONN HEADER EH TOP 2POS 2.5MM; Pin Cnt: 2; Pin Spacing: 2.5mm; Row Cnt: 1; Type: header; Vendor: JST
L5 L7 = PAS,INDUCTOR,_large: DigiKey: 541-1221-1-ND; DigiReel: 541-1221-6-ND; Family: passive; Index PN: 1274; Lead Style: SMT; MFG: Vishay/Dale; P/D_NUM: IHLP2020BZER3R3M11; Part Number: IHLP2020BZER3R3M11; Part Specific: FIXED IND 3.3UH 4.1A 57.8 MOHM; Type: inductor; VENDOR: Vishay/Dale; VPC: 4.1A
L6 = PAS,INDUCTOR,_large: DigiKey: 541-1221-1-ND; DigiReel: 541-1221-6-ND; Family: passive; Index PN: 1274; Lead Style: SMT; MFG: Vishay/Dale; P/D_NUM: IHLP2020BZER3R3M11; Part Number: IHLP2020BZER3R3M11; Part Specific: FIXED IND 3.3UH 4.1A 57.8 MOHM; Type: inductor; VENDOR: Vishay Dale; VPC: 4.1A
L8 = PAS,INDUCTOR,_large: DigiKey: ---; DigiReel: ---; Family: passive; Lead Style: SMT; MFG: Coilcraft; P/D_NUM: XAL7030-272MEB; Part Number: XAL7030-272MEB; Part Specific: INDUCTOR 2.7uH 9.2A 20% SMD; Tolerance: 20%; Type: inductor; VENDOR: Coilcraft; VPC: 9.2A
L10 = PAS,INDUCTOR,_large: DigiKey: ---; DigiReel: ---; Family: passive; Lead Style: SMT; MFG: Coilcraft; P/D_NUM: LPS4018-103MRB; Part Number: LPS4018-103MRB; Part Specific: INDUCTOR 10UH 20% 0.9A SMD; Type: inductor; VENDOR: Coilcraft; VPC: 0.9A
R79 = PAS,R,large: DigiKey: P300LCT-ND; DigiReel: P300LDKR-ND; Family: passive; Index PN: 1053; Lead Style: SMT; MFG: Panasonic; Material: chip; P/D_NUM: ERJ-2RKF3000X; Part Number: ERJ-2RKF3000X; Part Specific: RES 300 OHM 1/10W 1% 0402 SMD; Tolerance: 1%; Type: resistor; VPC: 1/16W; Vendor: Panasonic
R80 R94 = PAS,R,large: DigiKey: RHM10.0ADCT-ND; DigiReel: RHM10.0ADDKR-ND; Family: passive; Install: Y; Lead Style: SMT; MFG: Rohm; Material: chip; P/D_NUM: ESR03EZPF10R0; Part Number: ESR03EZPF10R0; Part Specific: RES 10 OHM 1/4W 1% 0603 SMD; Power: 1/4W; TOLERANCE: 1%; Type: resistor; VPC: 1/4W; Vendor: Panasonic
R81 = PAS,R,large: DigiKey: P30.1LCT-ND; DigiReel: P30.1LDKR-ND; Family: passive; Index PN: 976; Lead Style: SMT; MFG: Panasonic; Material: chip; P/D_NUM: ERJ-2RKF30R1X; Part Number: ERJ-2RKF30R1X; Part Specific: RES 30.1 OHM 1/16W 1% 0402 SMD; Power: 1/16W; TOLERANCE: 1%; Type: resistor; VENDOR: Panasonic; VPC: 1/16W
R95 = PAS,R,large: DigiKey: P10.0KLCT-ND; DigiReel: P10.0KLDKR-ND; Family: passive; Index PN: 680; Lead Style: SMT; MFG: Panasonic; Material: chip; P/D_NUM: ERJ-2RKF1002X; Part Number: ERJ-2RKF1002X; Part Specific: RES SMD 10K OHM 1% 1/10W 0402; Power: 1/16W; Tolerance: 1%; Type: resistor; VPC: 1/16W; Vendor: Panasonic
R96 = PAS,R,large: DigiKey: RHM3.9AXCT-ND; DigiReel: RHM3.9AXDKR-ND; Family: passive; Install: Y; Lead Style: SMT; MFG: Rohm; Material: chip; P/D_NUM: ESR25JZPJ3R9; Part Number: ESR25JZPJ3R9; Part Specific: RES 3.9 OHM 1/2W 5% 1210 SMD; Power: 1/2W; TOLERANCE: 5%; Type: resistor; VPC: 1/2W; Vendor: Rohm
R102 = PAS,R,large: DigiKey: CSRN2010FK25L0CT-ND; DigiReel: CSRN2010FK25L0DKR-ND; Family: passive; Lead Style: SMT; MFG: Stackpole Electronics; P/D_NUM: CSRN2010FK25L0; Part Number: CSRN2010FK25L0; Part Specific: RES SMD 0.025 OHM 1% 1W 2010; Tolerance: 1%; Type: resistor; VPC: 1W; Vendor: Stackpole Electronics
R103 = PAS,R,large: DigiKey: P100LCT-ND; DigiReel: P100LDKR-ND; Family: passive; Install: Y; Lead Style: SMT; MFG: Panasonic; Material: chip; P/D_NUM: ERJ-2RKF1000X; Part Number: ERJ-2RKF1000X; Part Specific: RES 100 OHM 1/10W 1% 0402 SMD; Power: 1/10W; TOLERANCE: 1%; Type: resistor; VPC: 1/10W; Vendor: Panasonic
R575 = PAS,R,large: DigiKey: P5.10KLCT-ND; DigiReel: P5.10KLDKR-ND; Family: passive; Lead Style: SMT; MFG: Panasonic; Material: chip; P/D_NUM: ERJ-2RKF5101X; Part Number: ERJ-2RKF5101X; Part Specific: RES 5.10K OHM 1/10W 1% 0402 SMD; Power: 1/10W; Tolerance: 1%; Type: resistor; VPC: 1/10W; Vendor: Panasonic
TP1-TP7 TP9 TP11 TP12 TP51-TP58 = BF,HOLE,PLATED,TESTPIN: DigiKey: ---; DigiReel: ---; Family: board feature; Index PN: 377; Install: DNI; Lead Style: TH; MFG: -- NOT A PART --; Type: hole,plated; Vendor: -- NOT A PART --
U40 = TIDLP,PAD3000_V2_5: DigiKey: 296-42431-5-ND; DigiReel: ---; Family: power; Index PN: 1293; Lead Style: SMT; MFG: Texas Instruments; P/D_NUM: DLPA3000DPFD; Part Number: DLPA3000DPFD; Part Specific: DLP PMIC, LED Driver IC; Pin Cnt: 100; Pin Spacing: 0.4mm; Type: regulator; Vendor: Texas Instruments; Color: Default; Install: Y; Location X-Coordinate: 0; Location Y-Coordinate: 0; Power Pins Visible: False; Primitive: DEFAULT; SPLIT_INST: TRUE; SWAP_INFO: (S1+S2)
C1 C10 C19 C33 C503 C513 C518 C531 = PAS,CAP,NP,large: DigiKey: 1276-1195-1-ND; DigiReel: 1276-1195-6-ND; Family: passive; Lead Style: SMT; MFG: Samsung; Material: x7r; P/D_NUM: CL10B102KA8NNNC; Part Number: CL10B102KA8NNNC; Part Specific: CAP CER 1000PF 25V 10% X7R 0603; TOLERANCE: 10%; Type: capacitor; VENDOR: Samsung; VOLTAGE: 25 V; VPC: 25 V
C2 C8 C20 C24 = PAS,CAP,NP,large: DigiKey: 478-1395-1-ND; DigiReel: 478-1395-6-ND; Family: passive; Lead Style: SMT; MFG: AVX; Material: x7r; P/D_NUM: 08055C104KAT2A; Part Number: 08055C104KAT2A; Part Specific: CAP CER 0.1UF 50V 10% X7R 0805; TOLERANCE: 10%; Type: capacitor; VENDOR: AVX; VPC: 50V
C502 C505-C507 C509 C519-C524 C526 C528-C530 C532-C534 = PAS,CAP,NP,large: DigiKey: 445-5942-1-ND; DigiReel: 445-5942-6-ND; Family: passive; Index PN: 1280; Lead Style: SMT; MFG: TDK; Material: x5r; P/D_NUM: C1005X5R1H104K050BB; Part Number: C1005X5R1H104K050BB; Part Specific: CAP CER 0.1UF 50V 10% X5R 0402; TOLERANCE: 10%; Type: capacitor; VENDOR: TDK; VPC: 50V
J1 = EM,CONN,18P+2G,1R,FLEX,2X_3: DigiKey: WM11113CT-ND; DigiReel: WM11113DKR-ND; Family: electro/mechanical; Install: DNI; Lead Style: SMT; MFG: Molex; Part Specific: CONN FFC FPC 18POS 0.50MM R/A; Pin Cnt: 18; Pin Spacing: 0.5mm; Row Cnt: 1; Type: connector; Vendor: Molex
J5 = EM,CONN,12P+2G,1R,FLEX,2X: DigiKey: WM1441CT-ND; DigiReel: WM1441DKR-ND; Family: electro/mechanical; Lead Style: SMT; MFG: Molex; Part Specific: CONN FFC FPC 12POS 0.50MM R/A; Pin Cnt: 12; Pin Spacing: 0.5mm; Row Cnt: 1; Type: connector; Vendor: Molex
R1 R18 R22 R38 = PAS,R,large: DigiKey: P1.0KGCT-ND; DigiReel: P1.0KGDKR-ND; Family: passive; Install: Y; Lead Style: SMT; MFG: Panasonic; Material: chip; P/D_NUM: ERJ-3GEYJ102V; Part Number: ERJ-3GEYJ102V; Part Specific: RES 1K OHM 5% 1/10W 0603 SMD; Power: 1/10W; TOLERANCE: 5%; Type: resistor; VENDOR: Panasonic; VPC: 1/10W
R2 R19 R23 R27 = PAS,R,large: DigiKey: 541-1894-1-ND; DigiReel: 541-1894-6-ND; Family: passive; Install: Y; Lead Style: SMT; MFG: Vishay Dale; Material: chip; P/D_NUM: TNPW08059K88BEEN; Part Number: TNPW08059K88BEEN; Part Specific: RES 9.88K OHM 0.1% 1/5W 0805 SMD; Power: 1/5W; TOLERANCE: 0.1%; Type: resistor; VENDOR: Vishay Dale; VPC: 1/5W
R3 R20 R28 R33 = PAS,R,large: DigiKey: P10.0KHCT-ND; DigiReel: P10.0KHDKR-ND; Family: passive; Lead Style: SMT; MFG: Panasonic; P/D_NUM: ERJ-3EKF1002V; Part Number: ERJ-3EKF1002V; Part Specific: RES 10K OHM 1% 1/10W 0603 SMD; Power: 1/10W; TOLERANCE: 1%; Type: resistor; VENDOR: Panasonic; VPC: 1/10W
R4 R21 R30 R32 = PAS,R,large: DigiKey: P33.0KLCT-ND; DigiReel: P33.0KLDKR-ND; Family: passive; Lead Style: SMT; MFG: Panasonic; Material: chip; P/D_NUM: ERJ-2RKF3302X; Part Number: ERJ-2RKF3302X; Part Specific: RES 33.0K OHM 1/10W 1% 0402 SMD; TOLERANCE: 1%; Type: resistor; VENDOR: Panasonic; VPC: 1/10W
R5 R29 R31 R39 R509 R525 = PAS,R,large: DigiKey: P0.0JCT-ND; DigiReel: P0.0JDKR-ND; Family: passive; Index PN: 687; Install: DNI; Lead Style: SMT; MFG: Panasonic; Material: chip; P/D_NUM: ERJ-2GE0R00X; Part Number: ERJ-2GE0R00X; Part Specific: RES 0.0 OHM 1/16W 0402 SMD; Power: 1/16W; Type: resistor; VPC: 1/16W; Vendor: Panasonic
R500 R513 R523 R528 = PAS,R,large: DigiKey: P76.8KHCT-ND; DigiReel: P76.8KHDKR-ND; Family: passive; Lead Style: SMT; MFG: Panasonic; Material: chip; P/D_NUM: ERJ-3EKF7682V; Part Number: ERJ-3EKF7682V; Part Specific: RES SMD 76.8K OHM 1% 1/10W 0603; Power: 1/10W; TOLERANCE: 1%; Type: resistor; VENDOR: Panasonic; VPC: 1/10W
R503 R514 R521 R530 = PAS,R,large: DigiKey: P100GCT-ND; DigiReel: P100KGDKR-ND; Family: passive; Install: Y; Lead Style: SMT; MFG: Panasonic; Material: chip; P/D_NUM: ERJ-3GEYJ101V; Part Number: ERJ-3GEYJ101V; Part Specific: RES 100 OHM 5% 1/10W 0603 SMD; Power: 1/10W; TOLERANCE: 5%; Type: resistor; VENDOR: Panasonic; VPC: 1/10W
R505 R511 R515 R532 = PAS,R,large: DigiKey: P19307CT-ND; DigiReel: P19307DKR-ND; Family: passive; Lead Style: SMT; MFG: Panasonic; P/D_NUM: ERJ-6DQFR91V; Part Number: ERJ-6DQFR91V; Part Specific: RES 0.91 OHM 1% 1/2W 0805 SMD; Power: 1/2W; Type: resistor; VENDOR: Panasonic; VPC: 1/2W
R510 R526 = PAS,R,large: DigiKey: P1.00KLCT-ND; DigiReel: P1.00KLDKR-ND; Family: passive; Index PN: 684; Install: DNI; Lead Style: SMT; MFG: Panasonic; Material: chip; P/D_NUM: ERJ-2RKF1001X; Part Number: ERJ-2RKF1001X; Part Specific: RES 1.00K OHM 1/10W 1% 0402 SMD; Power: 1/16W; TOLERANCE: 1%; Type: resistor; VENDOR: Panasonic; VPC: 1/16W
U1 U7 U8 U16 = ANA,OPAMP,TCA0372,SOIC16W,large: DigiKey: TCA0372DWGOS-ND; DigiReel: TCA0372DWR2GOSDKR-ND; Family: analog; Index PN: 1360; Lead Style: SMT; MFG: ON Semiconductor; P/D_NUM: TCA0372DWG; Part Number: TCA0372DWG; Part Specific: IC OPAMP GP 1.4MHZ 16SOIC; Type: opamp; Vendor: ON Semiconductor
U2 U3 U6 U9-U12 U17 = INF,DAC,DAC081S101: DigiKey: DAC081S101CIMK/NOPBTR-ND; Family: interface; Index PN: 1313; Lead Style: SMT; MFG: Texas Instruments; P/D_NUM: DAC081S101CIMK/NOPB; Part Number: DAC081S101CIMK/NOPB; Part Specific: CONV D/A 8BIT MICRO PWR TSOT23-6; Type: dac; Vendor: Texas Instruments

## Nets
DGND: C2.1(P) C8.1(P) C9.2(N) C20.1(P) C21.2(N) C22.2(N) C24.1(P) C34.2(N) C41.2(N) C42.2(N) C49.2(N) C60.2(N) C61.2(N) C63.2(N) C64.2(N) C65.2(N) C72.2(N) C74.2(N) C502.2(N) C505.2(N) C506.2(N) C507.2(N) C508.2(N) C509.2(N) C512.2(N) C519.2(N) C520.2(N) C521.2(N) C522.2(N) C523.2(N) C524.2(N) C525.2(N) C526.2(N) C528.2(N) C529.2(N) C530.2(N) C532.2(N) C533.2(N) C534.2(N) C535.2(N) C536.2(N) C548.2(N) C565.2(N) C573.2(N) C574.2(N) C575.2(N) C607.2(N) C608.2(N) C609.2(N) C610.2(N) C611.2(N) C612.2(N) C613.2(N) C614.2(N) C615.2(N) C616.2(N) C617.1(P) C618.1(P) C655.2(N) C656.2(N) C657.2(N) C658.2(N) C659.2(N) C660.2(N) C661.2(N) C662.2(N) C663.1(P) C664.2(N) C665.2(N) C666.2(N) C667.2(N) C668.2(N) C669.2(N) C670.2(N) D4.2(P2) D5.2(P2) D6.2(P2) J1.5(P5) J1.14(P14) J1.19(P19) J1.20(P20) J5.9(P9) J5.13(P13) J5.14(P14) J9.2 J500.G1 J500.G2 J500.G3 J500.G4 R3.1(N1) R20.1(N1) R28.1(N1) R33.1(N1) R80.2(N2) R94.2(N2) R96.1(N1) R102.1(N1) R505.1(N1) R511.1(N1) R515.1(N1) R532.1(N1) R600.2(N2) R616.1(N1) R617.1(N1) U2.2(GND) U3.2(GND) U6.2(GND) U9.2(GND) U10.2(GND) U11.2(GND) U12.2(GND) U17.2(GND) U40.4(DRST_PGND) U40.12(RLIM_BOT_K_2) U40.14(RLIM_BOT_K_1) U40.32(ILLUM_A_PGND) U40.37(ILLUM_B_PGND) U40.42(THERMAL_PAD) U40.54(PWR7_PGND) U40.59(DGND) U40.62(PWR6_PGND) U40.70(PWR5_PGND) U40.73(PWR2_PGND) U40.86(AGND) U40.93(PWR1_PGND) ; also on sheet 1 2 4 7 11 12 13 14 15 16 17
P5V: C613.1(P) C614.1(P) C669.1(P) J500.8(P8) J500.10(P10) U40.88(PWR3_VIN) U40.90(PWR4_VIN) ; also on sheet 2 11
P12V: C9.1(P) C21.1(P) C22.1(P) C34.1(P) C507.1(P) C520.1(P) C524.1(P) C534.1(P) U1.1(VCC+) U7.1(VCC+) U8.1(VCC+) U16.1(VCC+) ; also on sheet 2 11
P19V: C573.1(P) C574.1(P) C607.1(P) C608.1(P) C609.1(P) C610.1(P) C611.1(P) C612.1(P) C655.1(P) C656.1(P) C657.1(P) C658.1(P) C659.1(P) C660.1(P) C661.1(P) C662.1(P) C665.1(P) C668.1(P) J500.1(P1) J500.2(P2) J500.3(P3) J500.4(P4) J500.5(P5) J500.6(P6) U40.5(DRST_VIN) U40.8(ILLUM_VIN) U40.30(ILLUM_A_VIN) U40.34(ILLUM_B_VIN) U40.64(PWR6_VIN) U40.75(PWR2_VIN) U40.83(PWR_VIN) U40.85(VIN_SYSPWR) U40.96(PWR1_VIN) ; also on sheet 11
3DREF: J500.32(P32) TP46.1(P1) U26.H15(IO_0_34)
ACT_I2C_SCL: J1.12(P12) J5.7(P7) ; also on sheet 16
ACT_I2C_SDA: J1.13(P13) J5.8(P8) ; also on sheet 16
ACT_P3P3V: J5.5(P5) R525.2(N2)
ACT_P3P3V_1: J1.10(P10) R509.2(N2)
ACT_WP: J5.6(P6) R526.2(N2)
ACT_WP_1: J1.11(P11) R510.2(N2)
AUX_SPI_CLK: J500.19(P19) ; also on sheet 17
AUX_SPI_CSZ: J500.21(P21) ; also on sheet 17
AUX_SPI_MISO: J500.17(P17) ; also on sheet 17
AUX_SPI_MOSI: J500.15(P15) ; also on sheet 17
BLU_CATHODE: D5.1(P1) J10.4 J10.5 J10.6 U40.24(CH3_SWITCH_1) U40.25(CH3_SWITCH_2)
CMP_OUT: U40.81(ACMPR_OUT) ; also on sheet 4
CMPR_REF: R95.2(N2) U40.82(ACMPR_REF)
COIL_A_N: J1.2(P2) J5.2(P2) R38.2(N2) R532.2(N2) TP7.1(P1) U16.10(A_IN-)
COIL_A_P: C33.2(N) J1.1(P1) J5.1(P1) TP9.1(P1) U16.16(A_OUT)
COIL_A_PRE: C531.2(N) R27.1(N1) U16.2(B_OUT) U16.9(A_IN+)
COIL_B_N: J1.18(P18) R1.2(N2) R505.2(N2) TP1.1(P1) U1.10(A_IN-)
COIL_B_P: C1.2(N) J1.17(P17) TP2.1(P1) U1.16(A_OUT)
COIL_B_PRE: C503.2(N) R2.1(N1) U1.2(B_OUT) U1.9(A_IN+)
COIL_C_N: J1.16(P16) J5.4(P4) R22.2(N2) R511.2(N2) TP5.1(P1) U7.10(A_IN-)
COIL_C_P: C10.2(N) J1.15(P15) J5.3(P3) TP4.1(P1) U7.16(A_OUT)
COIL_C_PRE: C518.2(N) R23.1(N1) U7.2(B_OUT) U7.9(A_IN+)
COIL_D_N: J1.4(P4) R18.2(N2) R515.2(N2) TP3.1(P1) U8.10(A_IN-)
COIL_D_P: C19.2(N) J1.3(P3) TP6.1(P1) U8.16(A_OUT)
COIL_D_PRE: C513.2(N) R19.1(N1) U8.2(B_OUT) U8.9(A_IN+)
DAC_1A_DATA: U10.4(DIN) U17.4(DIN) ; also on sheet 16
DAC_1A_OUT: R27.2(N2) R30.2(N2) R530.2(N2) U16.7(B_IN-)
DAC_1A_REF: C20.2(N) R28.2(N2) R39.2(N2) R528.1(N1) U16.8(B_IN+)
DAC_1A_REF_SYNCZ: U17.6(~{SYNC}) ; also on sheet 16
DAC_1A_SCLK: U10.5(SCLK) U17.5(SCLK) ; also on sheet 16
DAC_1A_SYNCZ: U10.6(~{SYNC}) ; also on sheet 16
DAC_1A_VOUT: R30.1(N1) U10.1(VOUT)
DAC_1A_VREF: R39.1(N1) U17.1(VOUT)
DAC_1B_DATA: U2.4(DIN) U3.4(DIN) ; also on sheet 16
DAC_1B_OUT: R2.2(N2) R4.2(N2) R503.2(N2) U1.7(B_IN-)
DAC_1B_REF: C2.2(N) R3.2(N2) R5.2(N2) R500.1(N1) U1.8(B_IN+)
DAC_1B_REF_SYNCZ: U3.6(~{SYNC}) ; also on sheet 16
DAC_1B_SCLK: U2.5(SCLK) U3.5(SCLK) ; also on sheet 16
DAC_1B_SYNCZ: U2.6(~{SYNC}) ; also on sheet 16
DAC_1B_VOUT: R4.1(N1) U2.1(VOUT)
DAC_1B_VREF: R5.1(N1) U3.1(VOUT)
DAC_2A_DATA: U11.4(DIN) U12.4(DIN) ; also on sheet 16
DAC_2A_OUT: R23.2(N2) R32.2(N2) R521.2(N2) U7.7(B_IN-)
DAC_2A_REF: C24.2(N) R31.2(N2) R33.2(N2) R523.1(N1) U7.8(B_IN+)
DAC_2A_REF_SYNCZ: U11.6(~{SYNC}) ; also on sheet 16
DAC_2A_SCLK: U11.5(SCLK) U12.5(SCLK) ; also on sheet 16
DAC_2A_SYNCZ: U12.6(~{SYNC}) ; also on sheet 16
DAC_2A_VOUT: R32.1(N1) U12.1(VOUT)
DAC_2A_VREF: R31.1(N1) U11.1(VOUT)
DAC_2B_DATA: U6.4(DIN) U9.4(DIN) ; also on sheet 16
DAC_2B_OUT: R19.2(N2) R21.2(N2) R514.2(N2) U8.7(B_IN-)
DAC_2B_REF: C8.2(N) R20.2(N2) R29.2(N2) R513.1(N1) U8.8(B_IN+)
DAC_2B_REF_SYNCZ: U9.6(~{SYNC}) ; also on sheet 16
DAC_2B_SCLK: U6.5(SCLK) U9.5(SCLK) ; also on sheet 16
DAC_2B_SYNCZ: U6.6(~{SYNC}) ; also on sheet 16
DAC_2B_VOUT: R21.1(N1) U6.1(VOUT)
DAC_2B_VREF: R29.1(N1) U9.1(VOUT)
DAC_VREF: C502.1(P) C505.1(P) C521.1(P) C522.1(P) C528.1(P) C529.1(P) C530.1(P) C532.1(P) R500.2(N2) R513.2(N2) R523.2(N2) R528.2(N2) U2.3(VREF) U3.3(VREF) U6.3(VREF) U9.3(VREF) U10.3(VREF) U11.3(VREF) U12.3(VREF) U17.3(VREF) ; also on sheet 11
DATAEN: J500.36(P36) TP43.1(P1) U26.P18(IO_L20N_T3_34)
DRST_5P5V: C663.2(N) U40.3(DRST_5P5V)
DRST_HS: D10.1(P1) L10.1 U40.6(DRST_HS_IND)
DRST_LS: L10.2 U40.2(DRST_LS_IND)
EXT_SF0: R617.2(N2) TP40.1(P1) U26.M21(IO_L15P_T2_DQS_34)
EXT_SF1: R616.2(N2) TP42.1(P1) U26.L22(IO_L10N_T1_34)
FPGA_K16_PD: R600.1(N1) U26.K16(IO_L3P_T0_DQS_PUDC_B_34)
FPGA_SP_N19: TP41.1(P1) U26.N19(IO_L14P_T2_SRCC_34)
GRN_CATHODE: D4.1(P1) J8.4 J8.5 J8.6 U40.17(CH2_SWITCH_1) U40.18(CH2_SWITCH_2)
HOST_IRQ: J500.30(P30) ; also on sheet 13
HSYNC: J500.33(P33) TP28.1(P1) U26.P20(IO_L18P_T2_34)
I2C0_SCL: J500.28(P28) ; also on sheet 15
I2C0_SDA: J500.26(P26) ; also on sheet 15
ILLUM_5P5V: C72.1(P) U40.7(ILLUM_5P5V)
ILLUM_A_COMP1: C66.2(N) U40.38(ILLUM_A_COMP1)
ILLUM_A_COMP2: C66.1(P) U40.39(ILLUM_A_COMP2)
ILLUM_BOOST: C67.1(P) U40.28(ILLUM_A_BOOST) U40.33(ILLUM_B_BOOST)
ILLUM_SW: C67.2(N) C68.1(P) L8.2 TP54.1(P1) U40.31(ILLUM_A_SW) U40.36(ILLUM_B_SW)
INTZ: R575.1(N1) U40.58(INTZ) ; also on sheet 2 15
LABB_SAMPLE: U40.55(ACMPR_LABB_SAMPLE) ; also on sheet 4
LED_ANODE: C73.1(P) C74.1(P) C536.1(P) J8.1 J8.2 J8.3 J10.1 J10.2 J10.3 J11.1 J11.2 J11.3 L8.1 TP55.1(P1) U40.29(ILLUM_A_FB)
LED_SEL_0: U40.60(CH_SEL_0) ; also on sheet 4
LED_SEL_1: U40.61(CH_SEL_1) ; also on sheet 4
N12V: C506.1(P) C508.1(P) C512.1(P) C519.1(P) C523.1(P) C525.1(P) C533.1(P) C535.1(P) U1.4(VEE1) U1.5(VEE2) U1.12(VEE3) U1.13(VEE4) U7.4(VEE1) U7.5(VEE2) U7.12(VEE3) U7.13(VEE4) U8.4(VEE1) U8.5(VEE2) U8.12(VEE3) U8.13(VEE4) U16.4(VEE1) U16.5(VEE2) U16.12(VEE3) U16.13(VEE4) ; also on sheet 11
P1P1V_DLPA: C60.1(P) C61.1(P) L7.2 TP53.1(P1) U40.94(PWR1_FB) ; also on sheet 7
P1P8V_DLPA: C41.1(P) C64.1(P) C65.1(P) C565.1(P) L5.2 R575.2(N2) TP11.1(P1) U40.45(SPI_VIN) U40.72(PWR2_FB) ; also on sheet 1 2 4 7 13 15
P1P8V_SB: C670.1(P) J500.12(P12) ; also on sheet 17
P2P5V_DLPA: C615.1(P) TP51.1(P1) U40.87(PWR3_OUT) ; also on sheet 2 13
P3P3V: C509.1(P) C526.1(P) R509.1(N1) R510.1(N1) R525.1(N1) R526.1(N1) ; also on sheet 2 11 16
P3P3V_DLPA: C616.1(P) TP52.1(P1) U40.89(PWR4_OUT) ; also on sheet 2 4
P3P3V_SB: C575.1(P) J500.7(P7) J500.9(P9) ; also on sheet 2 7 15 17
PCLK: J500.34(P34) TP44.1(P1) U26.M19(IO_L13P_T2_MRCC_34)
PDATA0: J500.38(P38) U26.J16(IO_L2P_T0_34)
PDATA1: J500.37(P37) U26.J17(IO_L2N_T0_34)
PDATA2: J500.40(P40) U26.J15(IO_L1P_T0_34)
PDATA3: J500.39(P39) U26.K15(IO_L1N_T0_34)
PDATA4: J500.42(P42) U26.J18(IO_L7P_T1_34)
PDATA5: J500.41(P41) U26.J20(IO_L9P_T1_DQS_34)
PDATA6: J500.44(P44) U26.J21(IO_L8P_T1_34)
PDATA7: J500.43(P43) U26.J22(IO_L8N_T1_34)
PDATA8: J500.46(P46) U26.L18(IO_L12P_T1_MRCC_34)
PDATA9: J500.45(P45) U26.K18(IO_L7N_T1_34)
PDATA10: J500.48(P48) U26.K19(IO_L11P_T1_SRCC_34)
PDATA11: J500.47(P47) U26.K20(IO_L11N_T1_SRCC_34)
PDATA12: J500.50(P50) U26.K21(IO_L9N_T1_DQS_34)
PDATA13: J500.49(P49) U26.L16(IO_L3N_T0_DQS_34)
PDATA14: J500.52(P52) U26.L17(IO_L4P_T0_34)
PDATA15: J500.51(P51) U26.L21(IO_L10P_T1_34)
PDATA16: J500.54(P54) U26.M22(IO_L15N_T2_DQS_34)
PDATA17: J500.53(P53) U26.M15(IO_L6P_T0_34)
PDATA18: J500.56(P56) U26.M17(IO_L4N_T0_34)
PDATA19: J500.55(P55) U26.N17(IO_L5P_T0_34)
PDATA20: J500.58(P58) U26.N18(IO_L5N_T0_34)
PDATA21: J500.57(P57) U26.N22(IO_L16P_T2_34)
PDATA22: J500.60(P60) U26.P16(IO_L24P_T3_34)
PDATA23: J500.59(P59) U26.P17(IO_L20P_T3_34)
PDM_CVS_TE: J500.31(P31) TP45.1(P1)
PROJ_ON: J500.13(P13) U40.56(PROJ_ON) ; also on sheet 2 4
PWR1_B: C62.1(P) U40.97(PWR1_BOOST)
PWR1_SW: C59.2(N) C62.2(N) L7.1 U40.95(PWR1_SWITCH)
PWR2_B: C51.1(P) U40.76(PWR2_BOOST)
PWR2_SW: C50.2(N) C51.2(N) L5.1 U40.74(PWR2_SWITCH)
PWR6_B: C52.2(N) U40.65(PWR6_BOOST)
PWR6_OUT: C42.1(P) C548.1(P) J9.1 L6.1 TP12.1(P1) U40.66(PWR6_FB)
PWR6_SW: C52.1(P) L6.2 U40.63(PWR6_SWITCH)
PWR_5P5V: C63.1(P) U40.84(PWR_5P5V)
RC_CHARGE: R79.1(N1) ; also on sheet 4
RED_CATHODE: D6.1(P1) J11.4 J11.5 J11.6 U40.9(CH1_SWITCH_1) U40.10(CH1_SWITCH_2)
RESETZ: J500.14(P14) U40.57(RESET_Z) ; also on sheet 15 17
RLIM: R102.2(N2) R103.1(N1) U40.11(RLIM1_1) U40.16(RLIM1_2) U40.22(RLIM2_1) U40.23(RLIM2_2)
RLIM_K: C73.2(N) R103.2(N2) U40.13(RLIM_K_2) U40.15(RLIM_K_1)
SENS_FOCUS: U40.77(ACMPR_IN_1) ; also on sheet 4
SENS_LABB: U40.80(ACMPR_IN_LABB) ; also on sheet 4
SENS_THERM: U40.78(ACMPR_IN_2) ; also on sheet 4
SENS_WPC: U40.79(ACMPR_IN_3) ; also on sheet 4
SPI0_CLK: J500.22(P22) ; also on sheet 15
SPI0_CSZ0: J500.24(P24) ; also on sheet 15
SPI0_MISO: J500.20(P20) ; also on sheet 15
SPI0_MOSI: J500.18(P18) ; also on sheet 15
SPI1_CLK: U40.46(SPI_CLK) ; also on sheet 4
SPI1_CSZ0: U40.48(SPI_CS_Z) ; also on sheet 4
SPI1_DIN: R81.2(N2) ; also on sheet 4
SPI1_DOUT: U40.49(SPI_MOSI) ; also on sheet 4
SPI1_MISO: R81.1(N1) U40.47(SPI_MISO)
SUP_2P5V: C617.2(N) U40.91(SUP_2P5V)
SUP_5P0V: C618.2(N) U40.92(SUP_5P0V)
TSTPT_2: J500.11(P11) ; also on sheet 15
USB_AUX_SPI_OE_Z: J500.16(P16) R609.1(N1) TP49.1(P1)
USB_AUX_SPI_OEZ: R609.2(N2) ; also on sheet 17
VBIAS: C667.1(P) TP56.1(P1) U40.99(DMD_VBIAS) ; also on sheet 1
VOFS: C664.1(P) TP57.1(P1) U40.98(DMD_VOFFSET) ; also on sheet 1
VRST: C666.1(P) D10.2(P2) TP58.1(P1) U40.100(DMD_VRESET) ; also on sheet 1
VSYNC: J500.35(P35) TP27.1(P1) U26.P22(IO_L16N_T2_34)
N22457943: C59.1(P) R94.1(N1)
N22458021: C50.1(P) R80.1(N1)
N22458909: C68.2(N) R96.2(N2)
N22559120: C49.1(P) R79.2(N2) R95.1(N1)
N23494312: C33.1(P) R38.1(N1)
N23496200: C531.1(P) R530.1(N1)
N23498241: C10.1(P) R22.1(N1)
N23498325: C518.1(P) R521.1(N1)
N23555184: C1.1(P) R1.1(N1)
N23555280: C503.1(P) R503.1(N1)
N23557385: C19.1(P) R18.1(N1)
N23557469: C513.1(P) R514.1(N1)

Not connected (* = marked no-connect by the designer): J1 6(P6)* 7(P7)* 8(P8)* 9(P9)*; J5 10(P10)* 11(P11)* 12(P12)*; J500 23(P23)* 25(P25)* 27(P27)* 29(P29)*; U1 3(NC1)* 6(NC2)* 11(NC3)* 14(NC4)* 15(NC5)*; U7 3(NC1)* 6(NC2)* 11(NC3)* 14(NC4)* 15(NC5)*; U8 3(NC1)* 6(NC2)* 11(NC3)* 14(NC4)* 15(NC5)*; U16 3(NC1)* 6(NC2)* 11(NC3)* 14(NC4)* 15(NC5)*; U26 L19(IO_L12N_T1_MRCC_34) M16(IO_L6N_T0_VREF_34) M20(IO_L13N_T2_MRCC_34) N15(IO_L19P_T3_34) N20(IO_L14N_T2_SRCC_34) P15(IO_L19N_T3_VREF_34) P21(IO_L18N_T2_34) R15(IO_25_34) R16(IO_L24N_T3_34) R18(IO_L23P_T3_34) R19(IO_L22P_T3_34) R20(IO_L17P_T2_34) R21(IO_L17N_T2_34) T16(IO_L21P_T3_DQS_34) T17(IO_L21N_T3_DQS_34) T18(IO_L23N_T3_34) T19(IO_L22N_T3_34); U40 1(DRST_VRST_REF)* 19(CH1_GATE_CTRL)* 20(CH2_GATE_CTRL)* 21(CH3_GATE_CTRL)* 26(ILLUM_HSIDE_DRIVE)* 27(ILLUM_LSIDE_DRIVE)* 35(ILLUM_B_FB)* 40(ILLUM_B_COMP1)* 41(ILLUM_B_COMP2)* 43(CLK_OUT)* 44(CW_PWM_OUT)* 50(PWR7_BOOST)* 51(PWR7_FB)* 52(PWR7_VIN)* 53(PWR7_SWITCH)* 67(PWR5_VIN)* 68(PWR5_SWITCH)* 69(PWR5_BOOST)* 71(PWR5_FB)*

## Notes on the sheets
sheet 8
- TRP DMD:
- VOFS = 10V
- VBIAS = 18V
- VRST = -14V
- Place 0.47 caps close to
  their respective VIN pins.
- Connect the RLIM_K pins to the top of R103 with their own  traces.
  Also connect the RLIM_BOT_K pins to the bottom of the SENSE
  Resistor (R102) with their own traces. Consult the  DLPA3000 data
  sheet for details.
- 1.1V Supply for
  DLPC3436 Core
- 1.8V Supply for
  DLPC3436 & DMD
- DLPA3000
  5V Fan Power
- 2.5V Supply for
  DLPC3436 FPD-LINK
- DLPA3000 PMIC & LED Driver
- 3.3V Supply
sheet 9
- CONNECTION TO FRONT END PROVIDING PARALLEL RGB VIDEO INPUT
  (PLACE ON BOTTOM SIDE)
- RESERVED
- RESERVED
- RESERVED
- RESERVED
- VCCO_34 = P3P3V
- FPGA Parallel Data Input Interface
sheet 10
- 0.38V
- 0.38V
- DO NOT INSTALL.
  For engineering test
  purposes only.
- NOTE:
  THIS ACTUATOR DRIVER CIRCUIT IS PROVIDED
  "FOR EXAMPLE ONLY".
  THE ACTUAL DRIVER CIRCUIT REQUIRED FOR
  YOUR ACTUATOR IS SPECIFIED BY YOUR
  ACTUATOR  MANUFACTURER.
- 0.38V
- 0.38V
- ACTUATOR DRIVER
